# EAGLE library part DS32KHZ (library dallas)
32.768KHz Precision Oscillator w/battery backup
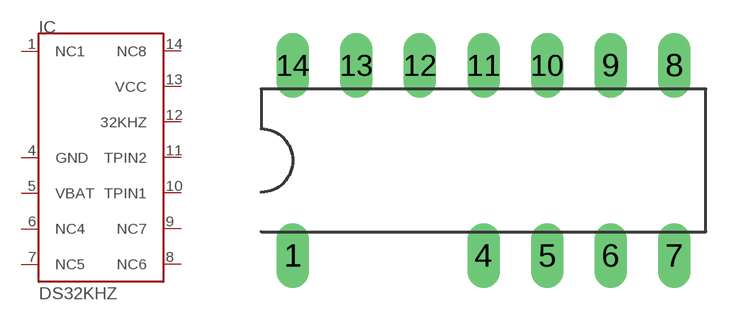
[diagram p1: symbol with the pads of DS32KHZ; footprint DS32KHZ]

Designator prefix IC

## DS32KHZ  [DS32KHZ]
1  NC1  nc
4  GND  pwr
5  VBAT  pwr
6  NC4  nc
7  NC5  nc
8  NC6  nc
9  NC7  nc
10  TPIN1  in
11  TPIN2  in
12  32KHZ  out
13  VCC  pwr
14  NC8  nc

## Footprint DS32KHZ (pad centres in mm)
drill 0.8 long: 1 -7.62,-3.81; 4 0,-3.81; 5 2.54,-3.81; 6 5.08,-3.81; 7 7.62,-3.81; 8 7.62,3.81; 9 5.08,3.81; 10 2.54,3.81; 11 0,3.81; 12 -2.54,3.81; 13 -5.08,3.81; 14 -7.62,3.81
